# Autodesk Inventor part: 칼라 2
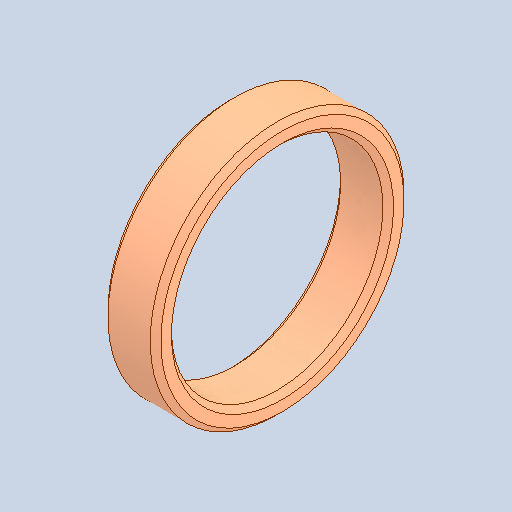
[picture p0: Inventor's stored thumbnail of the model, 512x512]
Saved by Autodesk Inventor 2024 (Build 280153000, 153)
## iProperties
Created: 2025-11
Part Number: 칼라 2
Material: 강철, 연강
Document SubType Name: Modeling
Designer: Eud07
Density: 7.85 g/cm^3
Appearance: 기본값
Author: jhkim
Sending System: Autodesk Inventor 2026
Preprocessor: ST-DEVELOPER v20.1
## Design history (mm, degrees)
node "칼라 21"
node "솔리드2"
node "솔리드1"
